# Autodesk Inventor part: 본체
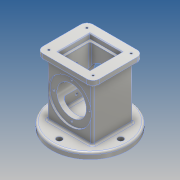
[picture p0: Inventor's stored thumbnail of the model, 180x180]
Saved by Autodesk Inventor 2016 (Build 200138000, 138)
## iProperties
Created: 2018-10
Part Number: 본체
Material: 알루미늄 6061
Document SubType Name: Modeling
Designer: Administrator
Density: 2.7 g/cm^3
Appearance: 알루미늄 - 평지
Mass: 984.574 g
Surface Area: 743.905 cm^2
Volume: 364.657 cm^3
Author: Administrator
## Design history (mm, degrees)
sketch "스케치1"
  geometry: L1 (-37, 33)-(37, 33); L2 (37, 33)-(37, -33); L3 (37, -33)-(-37, -33); L4 (-37, -33)-(-37, 33); L5 (-37, 33)-(37, -33); L6 (37, 33)-(-37, -33); 1 further point
  constraints: 12 end point, 2 midpoint, 2 parallel, 1 horizontal, 1 perpendicular
  dimensions: "d0" = 74 distance of L1.start L1.end; "d1" = 66 distance of L3.end L1.start
extrude "돌출1" new body sketch "스케치1" distance "d2" = 88; taper "d3" = 0 deg
sketch "스케치2"
  geometry: L1 (37, 33)-(-37, 33) reference; L2 (-37, 33)-(-37, -33) reference; L3 (-37, -33)-(37, -33) reference; L4 (37, -33)-(37, 33) reference; L5 (-46, 41)-(46, 41); L6 (46, 41)-(46, -41); L7 (46, -41)-(-46, -41); L8 (-46, -41)-(-46, 41); L9 (-46, 41)-(46, -41); L10 (46, 41)-(-46, -41); 1 further point
  constraints: 12 end point, 2 midpoint, 2 parallel, 1 horizontal, 1 perpendicular
  dimensions: "d4" = 92 distance of L5.start L5.end; "d5" = 82 distance of L5.end L6.end
extrude "돌출2" join sketch "스케치2" distance "d6" = 10; taper "d7" = 0 deg
sketch "스케치3"
  geometry: L1 (37, 33)-(-37, 33) reference; L2 (-37, 33)-(-37, -33) reference; L3 (-37, -33)-(37, -33) reference; L4 (37, -33)-(37, 33) reference; C1 r 62.5 at (0, 0); 1 further point
  constraints: 1 centre point, 1 coincident
  dimensions: "d8" = 125 diameter of C1
extrude "돌출3" join sketch "스케치3" distance "d9" = 10; taper "d10" = 0 deg
sketch "스케치4"
  geometry: 1 further point
sketch "스케치5"
  geometry: L1 (-46, 98)-(46, 98) reference; L2 (-62.5, -10)-(62.5, -10) reference; L3 (0, -10)-(0, 8); L4 (0, 8)-(-24.826, 8); L5 (-24.826, 8)-(-28, -10); L6 (0, -10)-(-28, -10); L7 (62.5, -10)-(-62.5, -10); L8 (0, 8)-(24.826, 8); L9 (24.826, 8)-(28, -10); L10 (0, -10)-(28, -10); 1 further point
  constraints: 16 end point, 4 symmetric about line, 2 point on line, 1 collinear, 1 midpoint, 1 perpendicular, 1 vertical
  dimensions: "d11" = 18 distance of L3.start L3.end; "d12" = 56 distance of L5.end L9.end; "d13" = 80 deg angle of L2 L9
revolve "회전1" sketch "스케치5" stored, may be unused: angle "d14" = 90 deg
fillet "모깎기1" dims "d15" = 3
sketch "스케치6"
  geometry: L1 (46, 41)-(-46, 41) reference; L2 (-46, 41)-(-46, -41) reference; L3 (-46, -41)-(46, -41) reference; L4 (46, -41)-(46, 41) reference; L5 (-26, 26)-(26, 26); L6 (26, 26)-(26, -26); L7 (26, -26)-(-26, -26); L8 (-26, -26)-(-26, 26); L9 (-26, 26)-(26, -26); L10 (26, 26)-(-26, -26); 1 further point
  constraints: 12 end point, 2 midpoint, 2 parallel, 1 horizontal, 1 perpendicular
  dimensions: "d17" = 52 distance of L5.start L5.end; "d18" = 52 distance of L7.end L5.start
extrude "돌출4" cut sketch "스케치6" distance "d19" = 8; taper "d20" = 0 deg
sketch "스케치8"
  geometry: L1 (74, -88)-(74, 0) reference; L2 (0, 0)-(74, 0) reference; L3 (0, -88)-(0, 0) reference; L4 (-25.5, -98)-(99.5, -98) reference; L5 (65, -98)-(9, -98) reference; L6 (37, -98)-(37, -44); L7 (74, -88)-(0, -88) reference; C1 r 35 at (37, -44); 1 further point
  constraints: 2 end point, 1 centre point, 1 coincident, 1 midpoint, 1 vertical
  dimensions: "d21" = 54 distance of L6.start L6.end; "d22" = 70 diameter of C1
extrude "돌출5" cut sketch "스케치8" distance "d23" = 3; taper "d24" = 0 deg
sketch "스케치9"
  geometry: C1 r 35 at (0, 0) reference; C2 r 24 at (0, 0); 1 further point
  constraints: 1 centre point, 1 coincident
  dimensions: "d25" = 48 diameter of C2
extrude "돌출6" cut sketch "스케치9" stored distance "d26" = 0; taper "d27" = 0 deg
sketch "스케치10"
  geometry: L1 (-26, 26)-(26, 26) reference; L2 (-26, -26)-(-26, 26) reference; L3 (26, -26)-(-26, -26) reference; L4 (26, 26)-(26, -26) reference; L5 (-19, 22)-(19, 22); L6 (22, 19)-(22, -19); L7 (19, -22)-(-19, -22); L8 (-22, -19)-(-22, 19); L9 (-22, 22)-(22, -22); L10 (22, 22)-(-22, -22); A1 r 3 centre (19, -19) between (19, -22) and (22, -19); A2 r 3 centre (19, 19) between (22, 19) and (19, 22); A3 r 3 centre (-19, 19) between (-19, 22) and (-22, 19); A4 r 3 centre (-19, -19) between (-22, -19) and (-19, -22); 1 further point
  constraints: 12 end point, 8 point on circle, 8 point on line, 8 tangent, 4 centre point, 3 equal radius, 2 midpoint, 2 parallel, 1 horizontal, 1 perpendicular
  dimensions: "d28" = 44 distance of L9.start L10.start; "d29" = 44 distance of L10.end L9.start; "d36" = 3 radius of A1
extrude "돌출7" cut sketch "스케치10" distance "d30" = 74; taper "d31" = 0 deg
fillet "모깎기3" dims "d32" = 10
fillet "모깎기4" dims "d33" = 3
fillet "모깎기5" dims "d34" = 3
fillet "모깎기6" dims "d35" = 3
chamfer "모따기1" distance "d37" = 1; stored, may be unused: second distance "d38" = 2, angle "d39" = 45 deg
sketch "스케치11"
  geometry: L1 (36, 41)-(-36, 41) reference; L2 (-46, 31)-(-46, -31) reference; L3 (-36, -41)-(36, -41) reference; L4 (46, -31)-(46, 31) reference; L5 (-27, 27)-(-27, -27) reference; L6 (27, 27)-(-27, 27) reference; L7 (27, -27)-(27, 27) reference; L8 (-27, -27)-(27, -27) reference; A1 r 10 centre (36, 31) between (46, 31) and (36, 41) reference; A2 r 10 centre (-36, 31) between (-36, 41) and (-46, 31) reference; A3 r 10 centre (-36, -31) between (-46, -31) and (-36, -41) reference; A4 r 10 centre (36, -31) between (36, -41) and (46, -31) reference; 5 further points
  constraints: 4 coincident
hole "구멍1" sketch "스케치11" at (-36, -31), (-36, 31), (36, 31), (36, -31) diameter "d40" = 3.242; stored, may be unused: countersink angle "d44" = 90 deg, drill point angle "d46" = 118 deg; dims "d41" = 4, "d42" = 4, "d43" = 2, "d45" = 6
sketch "스케치12" dims "d47" = 58
  geometry: L1 (0, 0)-(0, 29); C1 r 24 at (0, 0) reference; C2 r 35 at (0, 0) reference; 2 further points
  constraints: 2 coincident, 2 end point, 1 vertical, 1 vertical alignment, 2 other
hole "구멍2" sketch "스케치12" at (0, 29) diameter "d48" = 3.242; stored, may be unused: countersink angle "d52" = 90 deg, drill point angle "d54" = 118 deg; dims "d49" = 4, "d50" = 4, "d51" = 2, "d53" = 6
sketch "스케치13" dims "d58" = 100
  geometry: L1 (40, -30)-(40, 30) reference; L2 (-34, -36)-(34, -36) reference; L3 (-40, 30)-(-40, -30) reference; L4 (34, 36)-(-34, 36) reference; L5 (0, 0)-(0, -50); C1 r 59.5 at (0, 0) reference; C2 r 4.5 at (0, -50); A1 r 6 centre (34, 30) between (40, 30) and (34, 36) reference; A2 r 6 centre (34, -30) between (34, -36) and (40, -30) reference; A3 r 6 centre (-34, -30) between (-40, -30) and (-34, -36) reference; A4 r 6 centre (-34, 30) between (-34, 36) and (-40, 30) reference; 1 further point
  constraints: 2 coincident, 2 end point, 1 centre point, 1 vertical, 1 vertical alignment, 2 other
  dimensions: "d60" = 9 diameter of C2
extrude "돌출8" cut sketch "스케치13" stored distance "d61" = 74; taper "d62" = 0 deg
node "작업 평면1"
sketch "스케치15"
  geometry: L1 (72, 0)-(0, 0) reference; L2 (82, 0)-(72, 0) reference; L3 (82, 0)-(36, 0); L4 (36, 0)-(36, 4); 2 further points
  constraints: 4 end point, 1 coincident, 1 midpoint, 1 perpendicular, 1 other
  dimensions: "d76" = 46 distance of L2.start L3.end; "d77" = 4 distance of L3.end L4.end
feature "엠보싱1" sketch "스케치15" dims "d0" = 74, "d1" = 66, "d78" = 0.5, "d79" = 0
sketch "스케치16"
  geometry: L1 (82, 60)-(82, 0) reference; L2 (0, 60)-(82, 60) reference; L3 (0, 0)-(0, 60) reference; L4 (82, 0)-(0, 0) reference; L5 (-13, 92.5)-(-13, -32.5) reference; L6 (-13, 2)-(-13, 58) reference; L7 (-13, 30)-(24, 30); L8 (24, 30)-(67, 30); 3 further points
  constraints: 4 end point, 2 coincident, 1 horizontal, 1 midpoint, 1 point on line
  dimensions: "d80" = 37 distance of L7.start L7.end; "d81" = 43 distance of L7.end L8.end
hole "구멍4" sketch "스케치16" at (67, 30), (24, 30) diameter "d82" = 4.134; stored, may be unused: countersink angle "d86" = 90 deg, drill point angle "d88" = 118 deg; dims "d83" = 50, "d84" = 4, "d85" = 2, "d87" = 50
fillet "모깎기7" dims "d89" = 3
node "솔리드1"
mirror "대칭1"
pattern_circular "원형 패턴1" dims angle "d56" = 360 deg
mirror "대칭2"
pattern_circular "원형 패턴2" dims angle "d64" = 360 deg
node "투영된 루프1"
node "투영된 루프2"
node "투영된 루프3"
node "투영된 루프4"
node "투영된 루프5"
node "투영된 루프6"
node "투영된 루프7"
node "투영된 루프8"
node "투영된 루프9"
node "투영된 루프11"
other parameters: "d75" = 88, "d90" = 0.5, "d91" = 2, "d92" = 37
